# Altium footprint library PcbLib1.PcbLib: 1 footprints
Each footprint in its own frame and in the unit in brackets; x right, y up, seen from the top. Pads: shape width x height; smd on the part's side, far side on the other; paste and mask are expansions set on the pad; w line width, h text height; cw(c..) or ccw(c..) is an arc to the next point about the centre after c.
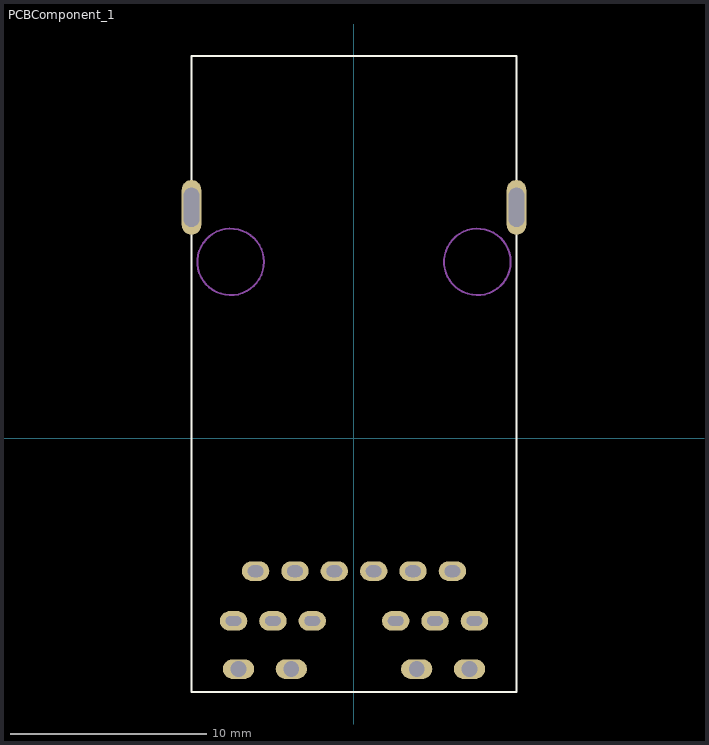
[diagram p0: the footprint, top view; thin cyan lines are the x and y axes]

## PCBComponent_1 [mm]
pads (18):
  oval 1x2.8 hole 0.8 slot 2 at 90 deg mask+0.01: ""(-8.3,11.79) ""(8.3,11.79)
  oval 1.4x1 hole 0.5 slot 0.8 at 0 deg mask+0.01: ""(-6.15,-9.33) ""(-4.14,-9.33) ""(-2.13,-9.33) ""(2.13,-9.33) ""(4.14,-9.33) ""(6.15,-9.33)
  oval 1.6x1 hole 0.8 mask+0.01: ""(-5.9,-11.79) ""(-3.2,-11.79) ""(3.2,-11.79) ""(5.9,-11.79)
  oval 1.4x1 hole 0.6 slot 0.8 at 0 deg: ""(-5.025,-6.79) ""(-3.015,-6.79) ""(-1.005,-6.79) ""(1.005,-6.79) ""(3.015,-6.79) ""(5.025,-6.79)
Top Overlay:
  lines w0.1: -8.3,-12.97 -8.3,19.53 8.3,19.53 8.3,-12.97 -8.3,-12.97
Mechanical 1:
  circle w0.1: c6.3,9.005 r1.7
  circle w0.1: c-6.3,9.005 r1.7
